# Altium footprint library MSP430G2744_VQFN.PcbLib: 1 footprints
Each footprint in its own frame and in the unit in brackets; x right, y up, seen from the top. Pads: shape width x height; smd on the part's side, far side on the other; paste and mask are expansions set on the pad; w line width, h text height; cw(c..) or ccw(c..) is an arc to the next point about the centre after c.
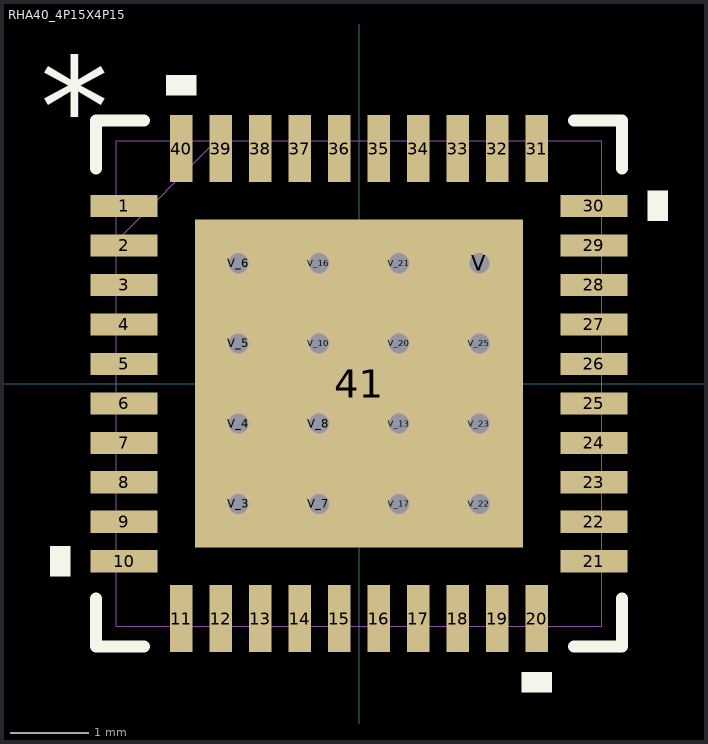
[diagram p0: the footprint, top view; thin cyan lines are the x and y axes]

## RHA40_4P15X4P15 [mm]
pads (57):
  rect 0.85x0.28 smd paste-0.14: 1(-2.975,2.25) 2(-2.975,1.75) 3(-2.975,1.25) 4(-2.975,0.75) 5(-2.975,0.25) 6(-2.975,-0.25) 7(-2.975,-0.75) 8(-2.975,-1.25) 9(-2.975,-1.75) 10(-2.975,-2.25) 21(2.975,-2.25) 22(2.975,-1.75) 23(2.975,-1.25) 24(2.975,-0.75) 25(2.975,-0.25) 26(2.975,0.25) 27(2.975,0.75) 28(2.975,1.25) 29(2.975,1.75) 30(2.975,2.25)
  rect 0.28x0.85 smd paste-0.14: 11(-2.251,-2.975) 12(-1.75,-2.975) 13(-1.25,-2.975) 14(-0.75,-2.975) 15(-0.25,-2.975) 16(0.25,-2.975) 17(0.75,-2.975) 18(1.25,-2.975) 19(1.75,-2.975) 20(2.251,-2.975) 31(2.251,2.975) 32(1.75,2.975) 33(1.25,2.975) 34(0.75,2.975) 35(0.25,2.975) 36(-0.25,2.975) 37(-0.75,2.975) 38(-1.25,2.975) 39(-1.75,2.975) 40(-2.251,2.975)
  rect 4.15x4.15 smd paste-2.062 mask-2.057: 41(0,0)
  round 0.356 hole 0.254: V(1.524,1.524) V_3(-1.524,-1.524) V_4(-1.524,-0.508) V_5(-1.524,0.508) V_6(-1.524,1.524) V_7(-0.508,-1.524) V_8(-0.508,-0.508) V_10(-0.508,0.508) V_13(0.508,-0.508) V_16(-0.508,1.524) V_17(0.508,-1.524) V_20(0.508,0.508) V_21(0.508,1.524) V_22(1.524,-1.524) V_23(1.524,-0.508) V_25(1.524,0.508)
Top Overlay:
  region: -2.06,3.654 -2.441,3.654 -2.441,3.908 -2.06,3.908
  region: 3.654,2.441 3.908,2.441 3.908,2.06 3.654,2.06
  region: 2.441,-3.654 2.06,-3.654 2.06,-3.908 2.441,-3.908
  region: -3.654,-2.06 -3.908,-2.06 -3.908,-2.441 -3.654,-2.441
  lines w0.152: -3.329,-2.723 -3.329,-3.329 -2.723,-3.329 ; -3.329,2.723 -3.329,3.329 -2.723,3.329 ; 2.723,-3.329 3.329,-3.329 3.329,-2.723 ; 2.723,3.329 3.329,3.329 3.329,2.723
  text "*" at -4.035,2.881 h1.27
Top Paste:
  drawing of 76 lines, arcs and shapes, not listed
Top Solder:
  drawing of 52 lines, arcs and shapes, not listed
Mechanical 1:
  lines w0: -3.075,1.805 -1.805,3.075 ; -3.075,-3.075 -3.075,3.075 3.075,3.075 3.075,-3.075 -3.075,-3.075 ; -3.075,-2.365 -3.075,-2.135 -3.075,-2.365 ; -3.075,-1.865 -3.075,-1.635 -3.075,-1.865 ; -3.075,-1.365 -3.075,-1.135 -3.075,-1.365 ; -3.075,-0.865 -3.075,-0.635 -3.075,-0.865 ; -3.075,-0.365 -3.075,-0.135 -3.075,-0.365 ; -3.075,0.135 -3.075,0.365 -3.075,0.135 ; -3.075,0.635 -3.075,0.865 -3.075,0.635 ; -3.075,1.135 -3.075,1.365 -3.075,1.135 ; -3.075,1.635 -3.075,1.865 -3.075,1.635 ; -3.075,2.135 -3.075,2.365 -3.075,2.135 ; -2.365,-3.075 -2.135,-3.075 -2.365,-3.075 ; -2.365,3.075 -2.135,3.075 -2.365,3.075 ; -1.865,-3.075 -1.635,-3.075 -1.865,-3.075 ; -1.865,3.075 -1.635,3.075 -1.865,3.075 ; -1.365,-3.075 -1.135,-3.075 -1.365,-3.075 ; -1.365,3.075 -1.135,3.075 -1.365,3.075 ; -0.865,-3.075 -0.635,-3.075 -0.865,-3.075 ; -0.865,3.075 -0.635,3.075 -0.865,3.075 ; -0.365,-3.075 -0.135,-3.075 -0.365,-3.075 ; -0.365,3.075 -0.135,3.075 -0.365,3.075 ; 0.135,-3.075 0.365,-3.075 0.135,-3.075 ; 0.135,3.075 0.365,3.075 0.135,3.075 ; 0.635,-3.075 0.865,-3.075 0.635,-3.075 ; 0.635,3.075 0.865,3.075 0.635,3.075 ; 1.135,-3.075 1.365,-3.075 1.135,-3.075 ; 1.135,3.075 1.365,3.075 1.135,3.075 ; 1.635,-3.075 1.865,-3.075 1.635,-3.075 ; 1.635,3.075 1.865,3.075 1.635,3.075 ; 2.135,-3.075 2.365,-3.075 2.135,-3.075 ; 2.135,3.075 2.365,3.075 2.135,3.075 ; 3.075,-2.365 3.075,-2.135 3.075,-2.365 ; 3.075,-1.865 3.075,-1.635 3.075,-1.865 ; 3.075,-1.365 3.075,-1.135 3.075,-1.365 ; 3.075,-0.865 3.075,-0.635 3.075,-0.865 ; 3.075,-0.365 3.075,-0.135 3.075,-0.365 ; 3.075,0.135 3.075,0.365 3.075,0.135 ; 3.075,0.635 3.075,0.865 3.075,0.635 ; 3.075,1.135 3.075,1.365 3.075,1.135 ; 3.075,1.635 3.075,1.865 3.075,1.635 ; 3.075,2.135 3.075,2.365 3.075,2.135
  text "*" at -4.035,2.881 h1.27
